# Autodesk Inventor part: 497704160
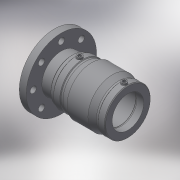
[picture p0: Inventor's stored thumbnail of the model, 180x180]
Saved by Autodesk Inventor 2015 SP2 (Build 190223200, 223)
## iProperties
Created: 2017-06
Part Number: 497704160
Material: Generic
Description: PLASSON PE CAST IRON SPIGOT COUPLER TRANSITION 225-200
Document SubType Name: Modeling
Designer: KIM
Mass: 55.0731 g
Surface Area: 148.067 cm^2
Volume: 55.0731 cm^3
Density: 1 g/cm^3
Appearance: Default
Author: KIM
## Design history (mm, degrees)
derived "497704.ipt"
feature "Solid1::497704.ipt"
tag "TaggingFeature1"
body "Solid1"
other parameters: "d13" = 195, "d14" = 17.6296, "d15" = 93, "d16" = 93, "d17" = 152, "d19" = 3.52592, "d20" = 168 deg, "d22" = 202.1, "d23" = 215, "d24" = 196.037, "d25" = 135 deg, "d26" = 78, "d27" = 135 deg, "d29" = 105, "d35" = 15, "d39" = 5 deg, "d45" = 4, "d46" = 14, "d47" = 0, "d50" = 3, "d51" = 0, "d52" = 26.97, "d53" = 6.7425, "d55" = 0.1, "d56" = 191.35, "d58" = 73, "d60" = 125, "d62" = 6.45, "d65" = 4.3, "d68" = 215, "d69" = 285, "d70" = 24, "d71" = 8, "d72" = 172.215, "d73" = 14.4, "d74" = 22, "d77" = 0, "d79" = 360 deg, "L_" = 268, "L_1" = 93, "D_1" = 215, "A_" = 105, "d_2" = 12, "L_2" = 73, "H_" = 109, "D_" = 285, "d_1" = 125, "t_" = 24, "S_" = 22
